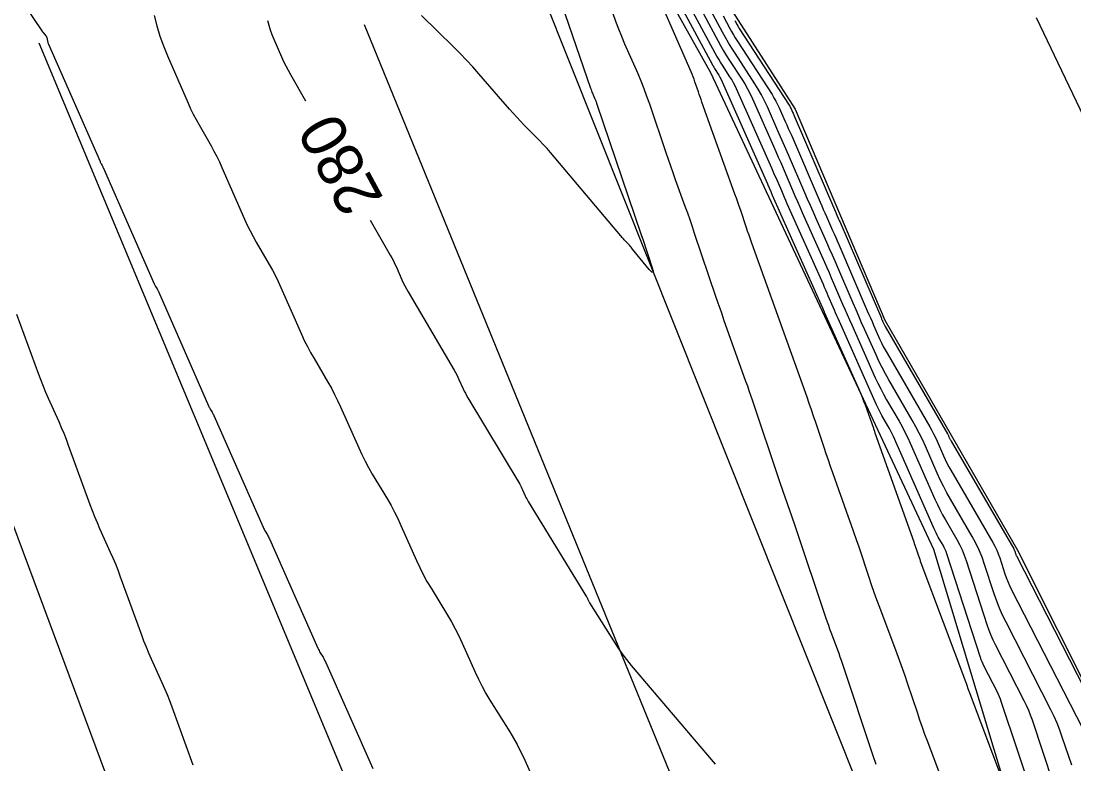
# Model space of a CAD drawing. Extents: x 1574966 to 1597594, y 720505 to 737840.
# Drawn here: x 1578007.3 to 1578146.9, y 724076.1 to 724174.6 of the extents above; entities that cross this region are included whole.
import ezdxf

# ---------------------------------------------------------------- set-up
doc = ezdxf.new("R2010")
doc.units = 0
for name, color, linetype in [('R_Contour Annot', 7, 'Continuous'), ('R_Contours', 7, 'Continuous'), ('S_BREAKLINE', 7, 'Continuous'), ('S_STREAM', 7, 'Continuous')]:
    doc.layers.add(name, color=color, linetype=linetype)

msp = doc.modelspace()

# ---------------------------------------------------------------- linework, layer by layer
at = {"layer": 'R_Contours'}
for points in [[(1577993.79, 724197.37), (1578010.08, 724173.27), (1578010.11, 724173.22), (1578010.14, 724173.18), (1578010.18, 724173.13), (1578010.21, 724173.09), (1578010.63, 724172.58), (1578010.66, 724172.54), (1578010.69, 724172.49), (1578010.71, 724172.44), (1578010.73, 724172.39), (1578010.84, 724171.89), (1578010.87, 724171.79), (1578010.9, 724171.69), (1578010.93, 724171.6), (1578010.97, 724171.5), (1578017.8, 724155.93), (1578017.83, 724155.86), (1578017.86, 724155.79), (1578017.9, 724155.73), (1578017.94, 724155.66), (1578018.08, 724155.4), (1578018.12, 724155.34), (1578018.15, 724155.27), (1578018.19, 724155.21), (1578018.22, 724155.14), (1578024.99, 724139.73), (1578025.03, 724139.64), (1578025.07, 724139.55), (1578025.11, 724139.47), (1578025.16, 724139.39), (1578025.35, 724139.06), (1578025.4, 724138.97), (1578025.44, 724138.89), (1578025.49, 724138.8), (1578025.53, 724138.72), (1578032.19, 724123.58), (1578032.24, 724123.47), (1578032.3, 724123.36), (1578032.35, 724123.26), (1578032.41, 724123.16), (1578032.65, 724122.75), (1578032.71, 724122.64), (1578032.77, 724122.54), (1578032.82, 724122.43), (1578032.87, 724122.32), (1578039.42, 724107.49), (1578039.48, 724107.36), (1578039.54, 724107.23), (1578039.61, 724107.1), (1578039.68, 724106.98), (1578039.98, 724106.48), (1578040.05, 724106.36), (1578040.12, 724106.23), (1578040.19, 724106.1), (1578040.25, 724105.97), (1578046.67, 724091.47), (1578046.74, 724091.31), (1578046.82, 724091.16), (1578046.9, 724091.01), (1578046.99, 724090.86), (1578047.35, 724090.27), (1578047.44, 724090.12), (1578047.52, 724089.97), (1578047.6, 724089.82), (1578047.67, 724089.66), (1578053.95, 724075.53)], [(1578129.94, 724072.6), (1578127.49, 724079.06), (1578127.13, 724080.02), (1578126.79, 724080.99), (1578126.45, 724081.96), (1578126.12, 724082.94), (1578124.82, 724086.84), (1578124.49, 724087.82), (1578124.15, 724088.79), (1578123.8, 724089.76), (1578123.45, 724090.72), (1578121.13, 724096.88), (1578120.77, 724097.87), (1578120.41, 724098.86), (1578120.06, 724099.86), (1578119.73, 724100.85), (1578118.39, 724104.85), (1578118.05, 724105.85), (1578117.71, 724106.84), (1578117.37, 724107.84), (1578117.01, 724108.83), (1578114.92, 724114.71), (1578114.63, 724115.54), (1578114.34, 724116.37), (1578114.05, 724117.21), (1578113.77, 724118.04), (1578112.65, 724121.38), (1578112.37, 724122.22), (1578112.08, 724123.05), (1578111.79, 724123.88), (1578111.5, 724124.71), (1578104.2, 724145.11), (1578104.01, 724145.65), (1578103.82, 724146.2), (1578103.63, 724146.74), (1578103.45, 724147.29), (1578102.71, 724149.47), (1578102.52, 724150.01), (1578102.33, 724150.56), (1578102.14, 724151.1), (1578101.95, 724151.64), (1578097.57, 724163.83), (1578097.45, 724164.16), (1578097.33, 724164.5), (1578097.21, 724164.83), (1578097.1, 724165.17), (1578096.64, 724166.51), (1578096.53, 724166.84), (1578096.4, 724167.18), (1578096.27, 724167.5), (1578096.13, 724167.83), (1578090.19, 724181.47)], [(1578077.48, 724181.14), (1578082.81, 724165.65), (1578082.87, 724165.48), (1578082.93, 724165.32), (1578083, 724165.15), (1578083.07, 724164.99), (1578083.35, 724164.33), (1578083.42, 724164.17), (1578083.49, 724164), (1578083.55, 724163.84), (1578083.61, 724163.67), (1578089.52, 724146.22), (1578089.53, 724146.19), (1578089.55, 724146.15), (1578089.56, 724146.11), (1578089.57, 724146.07), (1578089.63, 724145.92), (1578089.64, 724145.89), (1578089.65, 724145.85), (1578089.67, 724145.81), (1578089.68, 724145.78), (1578090.99, 724141.88), (1578091.12, 724141.42), (1578091.1, 724141.23), (1578090.92, 724141.31), (1578090.59, 724141.66), (1578088.39, 724144.35), (1578088.28, 724144.48), (1578088.17, 724144.61), (1578088.06, 724144.73), (1578087.95, 724144.85), (1578087.49, 724145.34), (1578087.38, 724145.46), (1578087.27, 724145.58), (1578087.16, 724145.71), (1578087.05, 724145.83), (1578077.99, 724156.57), (1578077.52, 724157.12), (1578077.04, 724157.66), (1578076.55, 724158.19), (1578076.05, 724158.71), (1578074.03, 724160.78), (1578073.53, 724161.3), (1578073.03, 724161.83), (1578072.55, 724162.36), (1578072.07, 724162.9), (1578068.02, 724167.56), (1578067.21, 724168.48), (1578066.37, 724169.38), (1578065.52, 724170.27), (1578064.65, 724171.14), (1578060.4, 724175.31)], [(1578092.43, 724180.89), (1578098.95, 724168.75), (1578099.04, 724168.6), (1578099.13, 724168.44), (1578099.22, 724168.28), (1578099.32, 724168.13), (1578099.72, 724167.52), (1578099.81, 724167.37), (1578099.9, 724167.21), (1578099.98, 724167.05), (1578100.06, 724166.89), (1578106.25, 724152.98), (1578106.31, 724152.85), (1578106.36, 724152.73), (1578106.42, 724152.6), (1578106.47, 724152.48), (1578106.68, 724151.98), (1578106.74, 724151.86), (1578106.79, 724151.73), (1578106.85, 724151.61), (1578106.9, 724151.49), (1578113.5, 724136.67), (1578113.53, 724136.62), (1578113.55, 724136.56), (1578113.58, 724136.51), (1578113.6, 724136.45), (1578113.69, 724136.23), (1578113.72, 724136.18), (1578113.74, 724136.12), (1578113.77, 724136.07), (1578113.79, 724136.01), (1578118.36, 724125.77), (1578118.58, 724125.26), (1578118.8, 724124.74), (1578119, 724124.22), (1578119.19, 724123.7), (1578120.29, 724120.64), (1578120.3, 724120.59), (1578120.32, 724120.54), (1578120.34, 724120.49), (1578120.36, 724120.43), (1578120.43, 724120.23), (1578120.44, 724120.18), (1578120.46, 724120.13), (1578120.48, 724120.07), (1578120.5, 724120.02), (1578125.64, 724105.57), (1578125.72, 724105.34), (1578125.8, 724105.11), (1578125.88, 724104.88), (1578125.96, 724104.64), (1578126.27, 724103.72), (1578126.35, 724103.48), (1578126.43, 724103.25), (1578126.51, 724103.02), (1578126.6, 724102.79), (1578132.5, 724087.05), (1578132.55, 724086.93), (1578132.59, 724086.82), (1578132.63, 724086.71), (1578132.67, 724086.59), (1578132.82, 724086.13), (1578132.86, 724086.02), (1578132.9, 724085.9), (1578132.94, 724085.79), (1578132.98, 724085.68), (1578137.63, 724073.38)], [(1578141.69, 724071.1), (1578137.24, 724084.43), (1578137.13, 724084.74), (1578137.01, 724085.04), (1578136.88, 724085.33), (1578136.74, 724085.63), (1578134.98, 724089.07), (1578134.84, 724089.35), (1578134.71, 724089.65), (1578134.59, 724089.94), (1578134.49, 724090.24), (1578130.04, 724103.97), (1578129.93, 724104.27), (1578129.81, 724104.55), (1578129.68, 724104.83), (1578129.53, 724105.11), (1578128.9, 724106.19), (1578128.75, 724106.46), (1578128.6, 724106.74), (1578128.46, 724107.02), (1578128.33, 724107.3), (1578122.95, 724119.52), (1578122.79, 724119.88), (1578122.61, 724120.24), (1578122.43, 724120.59), (1578122.23, 724120.94), (1578121.43, 724122.31), (1578121.24, 724122.66), (1578121.05, 724123.01), (1578120.88, 724123.37), (1578120.71, 724123.73), (1578115.61, 724135.15), (1578115.45, 724135.52), (1578115.28, 724135.9), (1578115.12, 724136.27), (1578114.96, 724136.65), (1578114.31, 724138.15), (1578114.15, 724138.52), (1578113.99, 724138.89), (1578113.82, 724139.27), (1578113.66, 724139.64), (1578108.88, 724150.35), (1578108.7, 724150.78), (1578108.51, 724151.2), (1578108.32, 724151.63), (1578108.14, 724152.06), (1578107.4, 724153.77), (1578107.21, 724154.2), (1578107.03, 724154.63), (1578106.84, 724155.06), (1578106.65, 724155.48), (1578102.16, 724165.57), (1578101.96, 724165.98), (1578101.75, 724166.39), (1578101.52, 724166.79), (1578101.28, 724167.18), (1578100.28, 724168.73), (1578100.03, 724169.12), (1578099.79, 724169.52), (1578099.56, 724169.92), (1578099.34, 724170.32), (1578094.61, 724179.1)], [(1578096.8, 724177.32), (1578099.72, 724171.89), (1578100.08, 724171.24), (1578100.45, 724170.6), (1578100.83, 724169.96), (1578101.23, 724169.34), (1578102.85, 724166.85), (1578103.24, 724166.22), (1578103.6, 724165.57), (1578103.95, 724164.92), (1578104.26, 724164.24), (1578107.04, 724157.99), (1578107.37, 724157.26), (1578107.69, 724156.53), (1578108.01, 724155.8), (1578108.32, 724155.07), (1578109.59, 724152.13), (1578109.9, 724151.4), (1578110.22, 724150.67), (1578110.54, 724149.94), (1578110.87, 724149.21), (1578113.81, 724142.61), (1578114.12, 724141.92), (1578114.42, 724141.23), (1578114.72, 724140.53), (1578115.02, 724139.84), (1578116.22, 724137.06), (1578116.52, 724136.37), (1578116.82, 724135.67), (1578117.13, 724134.98), (1578117.43, 724134.29), (1578120.55, 724127.31), (1578120.89, 724126.57), (1578121.26, 724125.83), (1578121.64, 724125.11), (1578122.04, 724124.39), (1578123.7, 724121.54), (1578124.1, 724120.83), (1578124.48, 724120.1), (1578124.84, 724119.36), (1578125.19, 724118.62), (1578128.45, 724111.2), (1578128.77, 724110.51), (1578129.1, 724109.83), (1578129.46, 724109.16), (1578129.83, 724108.49), (1578131.36, 724105.86), (1578131.72, 724105.19), (1578132.05, 724104.51), (1578132.34, 724103.81), (1578132.6, 724103.1), (1578135.39, 724094.49), (1578135.61, 724093.85), (1578135.86, 724093.21), (1578136.14, 724092.58), (1578136.44, 724091.96), (1578140.24, 724084.55), (1578140.54, 724083.92), (1578140.83, 724083.28), (1578141.08, 724082.63), (1578141.32, 724081.97), (1578144.12, 724073.57)], [(1578146.58, 724075.97), (1578145.33, 724079.7), (1578145.01, 724080.62), (1578144.64, 724081.53), (1578144.25, 724082.43), (1578143.82, 724083.31), (1578137.87, 724094.92), (1578137.42, 724095.84), (1578137.01, 724096.77), (1578136.64, 724097.72), (1578136.3, 724098.68), (1578135.04, 724102.58), (1578134.7, 724103.54), (1578134.31, 724104.48), (1578133.87, 724105.4), (1578133.38, 724106.29), (1578130.52, 724111.22), (1578130.04, 724112.06), (1578129.59, 724112.92), (1578129.16, 724113.79), (1578128.76, 724114.67), (1578127.2, 724118.22), (1578126.79, 724119.1), (1578126.37, 724119.97), (1578125.92, 724120.82), (1578125.44, 724121.67), (1578122.34, 724127.01), (1578121.88, 724127.82), (1578121.44, 724128.65), (1578121.03, 724129.48), (1578120.64, 724130.33), (1578119.12, 724133.74), (1578118.74, 724134.59), (1578118.36, 724135.45), (1578117.99, 724136.3), (1578117.62, 724137.16), (1578115.57, 724141.91), (1578115.22, 724142.73), (1578114.86, 724143.56), (1578114.49, 724144.38), (1578114.13, 724145.2), (1578112.66, 724148.49), (1578112.3, 724149.31), (1578111.94, 724150.14), (1578111.58, 724150.96), (1578111.22, 724151.79), (1578109.05, 724156.83), (1578108.7, 724157.63), (1578108.35, 724158.43), (1578108, 724159.23), (1578107.65, 724160.02), (1578106.24, 724163.2), (1578105.87, 724163.99), (1578105.47, 724164.76), (1578105.04, 724165.51), (1578104.58, 724166.25), (1578101.96, 724170.29), (1578101.52, 724170.98), (1578101.1, 724171.67), (1578100.69, 724172.37), (1578100.3, 724173.09), (1578098.76, 724175.95)], [(1578024.96, 724175.27), (1578025.31, 724173.91), (1578025.72, 724172.57), (1578026.19, 724171.25), (1578026.73, 724169.94), (1578029.48, 724163.67), (1578029.81, 724162.94), (1578030.16, 724162.22), (1578030.53, 724161.51), (1578030.92, 724160.81), (1578032.51, 724158.03), (1578032.9, 724157.33), (1578033.27, 724156.62), (1578033.62, 724155.9), (1578033.95, 724155.17), (1578036.96, 724148.31), (1578037.32, 724147.53), (1578037.69, 724146.77), (1578038.09, 724146.01), (1578038.51, 724145.27), (1578040.22, 724142.31), (1578040.64, 724141.57), (1578041.04, 724140.81), (1578041.41, 724140.05), (1578041.77, 724139.27), (1578044.49, 724133.08), (1578044.87, 724132.25), (1578045.28, 724131.44), (1578045.7, 724130.63), (1578046.16, 724129.84), (1578048.01, 724126.7), (1578048.46, 724125.91), (1578048.89, 724125.1), (1578049.29, 724124.29), (1578049.67, 724123.46), (1578052.08, 724118.01), (1578052.49, 724117.12), (1578052.92, 724116.25), (1578053.38, 724115.4), (1578053.87, 724114.55), (1578055.88, 724111.21), (1578056.37, 724110.36), (1578056.83, 724109.51), (1578057.27, 724108.64), (1578057.67, 724107.75), (1578059.73, 724103.11), (1578060.17, 724102.17), (1578060.63, 724101.24), (1578061.13, 724100.32), (1578061.67, 724099.42), (1578063.85, 724095.85), (1578064.38, 724094.95), (1578064.88, 724094.04), (1578065.35, 724093.11), (1578065.79, 724092.16), (1578067.51, 724088.3), (1578067.95, 724087.35), (1578068.43, 724086.41), (1578068.94, 724085.49), (1578069.48, 724084.59), (1578072.11, 724080.38), (1578072.61, 724079.57), (1578073.07, 724078.73), (1578073.5, 724077.88), (1578073.91, 724077.02), (1578075.46, 724073.53)], [(1578040.01, 724174.62), (1578040.17, 724174), (1578040.36, 724173.38), (1578040.58, 724172.77), (1578040.83, 724172.17), (1578041.87, 724169.8), (1578042.13, 724169.21), (1578042.42, 724168.63), (1578042.72, 724168.05), (1578043.03, 724167.48), (1578045.03, 724163.99)], [(1578120.64, 724076.06), (1578120.51, 724076.45), (1578120.38, 724076.84), (1578116.06, 724089.84), (1578115.9, 724090.3), (1578115.74, 724090.77), (1578115.57, 724091.23), (1578115.4, 724091.7), (1578114.71, 724093.54), (1578114.54, 724094), (1578114.37, 724094.46), (1578114.21, 724094.93), (1578114.05, 724095.4), (1578109.98, 724107.57), (1578109.81, 724108.08), (1578109.63, 724108.58), (1578109.46, 724109.09), (1578109.28, 724109.59), (1578108.56, 724111.61), (1578108.39, 724112.11), (1578108.21, 724112.62), (1578108.04, 724113.12), (1578107.86, 724113.63), (1578104.28, 724124.32), (1578104.07, 724124.94), (1578103.85, 724125.57), (1578103.64, 724126.19), (1578103.41, 724126.81), (1578100.49, 724134.98), (1578100.23, 724135.72), (1578099.97, 724136.46), (1578099.71, 724137.2), (1578099.46, 724137.95), (1578096.6, 724146.41), (1578096.3, 724147.31), (1578095.99, 724148.2), (1578095.68, 724149.09), (1578095.36, 724149.98), (1578094.08, 724153.54), (1578093.76, 724154.43), (1578093.45, 724155.32), (1578093.14, 724156.22), (1578092.83, 724157.11), (1578090.65, 724163.55), (1578090.29, 724164.57), (1578089.91, 724165.58), (1578089.52, 724166.58), (1578089.1, 724167.57), (1578087.37, 724171.51), (1578086.95, 724172.51), (1578086.55, 724173.5), (1578086.17, 724174.51), (1578085.81, 724175.52)], [(1578100.37, 724175.23), (1578101.27, 724173.56), (1578101.5, 724173.15), (1578101.74, 724172.74), (1578101.98, 724172.33), (1578102.24, 724171.93), (1578106.86, 724164.82), (1578107.12, 724164.4), (1578107.37, 724163.96), (1578107.59, 724163.52), (1578107.81, 724163.07), (1578108.62, 724161.24), (1578108.82, 724160.79), (1578109.02, 724160.33), (1578109.22, 724159.87), (1578109.42, 724159.42), (1578113.24, 724150.54), (1578113.45, 724150.07), (1578113.65, 724149.6), (1578113.85, 724149.14), (1578114.06, 724148.68), (1578114.89, 724146.82), (1578115.09, 724146.36), (1578115.3, 724145.89), (1578115.5, 724145.43), (1578115.7, 724144.96), (1578119.49, 724136.17), (1578119.69, 724135.69), (1578119.9, 724135.22), (1578120.11, 724134.74), (1578120.32, 724134.27), (1578121.16, 724132.38), (1578121.38, 724131.91), (1578121.61, 724131.45), (1578121.85, 724130.99), (1578122.1, 724130.54), (1578127.77, 724120.78), (1578128.03, 724120.32), (1578128.28, 724119.85), (1578128.51, 724119.37), (1578128.73, 724118.89), (1578129.59, 724116.95), (1578129.81, 724116.46), (1578130.04, 724115.99), (1578130.29, 724115.52), (1578130.55, 724115.05), (1578136.14, 724105.46), (1578136.4, 724104.97), (1578136.64, 724104.48), (1578136.85, 724103.97), (1578137.03, 724103.45), (1578137.72, 724101.34), (1578137.9, 724100.82), (1578138.1, 724100.31), (1578138.32, 724099.8), (1578138.56, 724099.3), (1578148.09, 724080.72)], [(1578101.92, 724174.64), (1578101.99, 724174.52), (1578102.24, 724174.04), (1578102.31, 724173.92), (1578102.38, 724173.8), (1578102.45, 724173.69), (1578102.52, 724173.57), (1578109.13, 724163.39), (1578109.2, 724163.28), (1578109.26, 724163.17), (1578109.32, 724163.05), (1578109.38, 724162.94), (1578109.58, 724162.47), (1578109.64, 724162.35), (1578109.69, 724162.23), (1578109.74, 724162.11), (1578109.79, 724162), (1578115.27, 724149.28), (1578115.31, 724149.18), (1578115.36, 724149.07), (1578115.41, 724148.96), (1578115.45, 724148.86), (1578115.64, 724148.44), (1578115.69, 724148.33), (1578115.73, 724148.22), (1578115.78, 724148.12), (1578115.83, 724148.01), (1578121.35, 724135.18), (1578121.39, 724135.08), (1578121.43, 724134.99), (1578121.48, 724134.9), (1578121.52, 724134.8), (1578121.68, 724134.43), (1578121.72, 724134.34), (1578121.77, 724134.25), (1578121.82, 724134.16), (1578121.87, 724134.07), (1578130.1, 724119.89), (1578130.15, 724119.81), (1578130.19, 724119.73), (1578130.23, 724119.65), (1578130.27, 724119.56), (1578130.42, 724119.22), (1578130.46, 724119.14), (1578130.5, 724119.06), (1578130.54, 724118.97), (1578130.59, 724118.89), (1578138.89, 724104.62), (1578138.93, 724104.55), (1578138.97, 724104.48), (1578139, 724104.4), (1578139.03, 724104.32), (1578139.13, 724104), (1578139.16, 724103.92), (1578139.19, 724103.84), (1578139.22, 724103.77), (1578139.26, 724103.69), (1578152.35, 724078.14)], [(1578053.59, 724148.16), (1578056.25, 724143.56), (1578056.48, 724143.17), (1578056.69, 724142.77), (1578056.89, 724142.36), (1578057.07, 724141.95), (1578057.8, 724140.29), (1578057.99, 724139.88), (1578058.19, 724139.48), (1578058.41, 724139.08), (1578058.63, 724138.69), (1578064.75, 724128.3), (1578064.92, 724128.01), (1578065.08, 724127.71), (1578065.23, 724127.4), (1578065.37, 724127.09), (1578065.92, 724125.85), (1578066.06, 724125.54), (1578066.22, 724125.24), (1578066.38, 724124.94), (1578066.55, 724124.64), (1578073.42, 724113.2), (1578073.52, 724113.02), (1578073.63, 724112.83), (1578073.72, 724112.63), (1578073.81, 724112.44), (1578074.16, 724111.65), (1578074.25, 724111.45), (1578074.35, 724111.26), (1578074.45, 724111.07), (1578074.56, 724110.89), (1578082.27, 724098.3), (1578082.31, 724098.23), (1578082.35, 724098.16), (1578082.39, 724098.09), (1578082.42, 724098.02), (1578082.54, 724097.74), (1578082.58, 724097.67), (1578082.61, 724097.6), (1578082.65, 724097.53), (1578082.69, 724097.47), (1578085.83, 724092.46), (1578086.38, 724091.61), (1578086.96, 724090.79), (1578087.57, 724089.98), (1578088.21, 724089.2), (1578099.34, 724076.1)], [(1578006.75, 724135.71), (1578009.66, 724127.76), (1578009.95, 724126.96), (1578010.27, 724126.17), (1578010.59, 724125.39), (1578010.93, 724124.61), (1578012.32, 724121.51), (1578012.66, 724120.73), (1578012.99, 724119.95), (1578013.3, 724119.16), (1578013.59, 724118.37), (1578016.46, 724110.5), (1578016.77, 724109.7), (1578017.08, 724108.91), (1578017.41, 724108.12), (1578017.75, 724107.33), (1578019.16, 724104.21), (1578019.5, 724103.43), (1578019.83, 724102.64), (1578020.14, 724101.84), (1578020.44, 724101.04), (1578023.28, 724093.26), (1578023.58, 724092.45), (1578023.9, 724091.65), (1578024.23, 724090.86), (1578024.58, 724090.07), (1578026, 724086.92), (1578026.35, 724086.13), (1578026.68, 724085.33), (1578027, 724084.53), (1578027.3, 724083.72), (1578030.1, 724076.04)]]:
    msp.add_lwpolyline(points, dxfattribs=at)
at = {"layer": 'S_BREAKLINE'}
for p, q in [((1578132.36, 724038.09), (1578075.05, 724181.63)), ((1578141.87, 724175.04), (1578155.58, 724146.25)), ((1578102.27, 724053.14), (1578052.83, 724174.07)), ((1577982.26, 724172.17), (1578035.49, 724029.31)), ((1578064.72, 724039.7), (1578009.73, 724171.63))]:
    msp.add_line(p, q, dxfattribs=at)
at = {"layer": 'S_STREAM'}
for p, q in [((1578065.75, 724226.72), (1578098.7, 724167.74)), ((1578095.35, 724185.57), (1578109.92, 724162.89)), ((1578098.7, 724167.74), (1578128.25, 724104.58)), ((1578109.92, 724162.89), (1578121.81, 724134.93)), ((1578121.81, 724134.93), (1578139.38, 724104.48)), ((1578128.25, 724104.58), (1578150.09, 724032.49)), ((1578139.38, 724104.48), (1578152.7, 724077.93))]:
    msp.add_line(p, q, dxfattribs=at)

# ---------------------------------------------------------------- texts
at = {"layer": 'R_Contour Annot'}
msp.add_text('280', height=6, rotation=118.4039, dxfattribs=at).set_placement((1578055.44, 724151.04))

doc.saveas('drawing.dxf')
